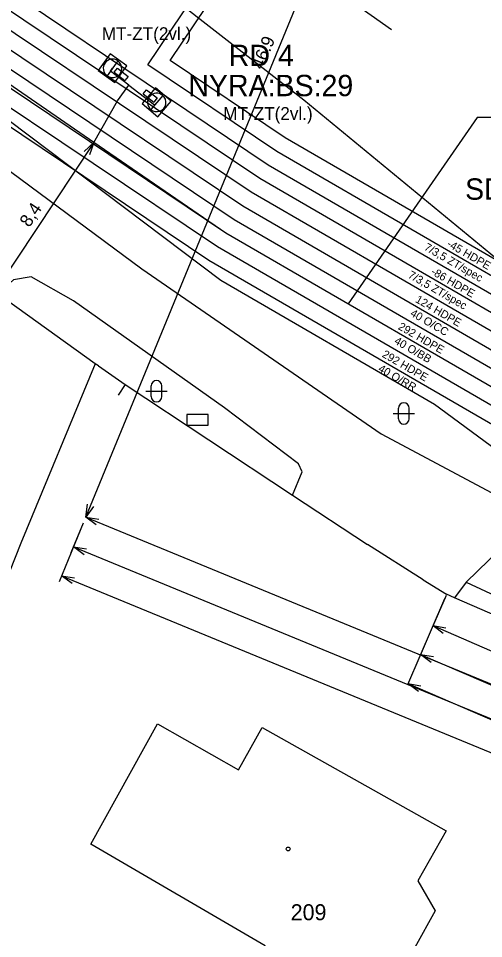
# Model space of a CAD drawing. Extents: x -836739 to -834468, y -1071001 to -1070126.
# Drawn here: x -836438.65 to -836416.85, y -1070403.2 to -1070360.1 of the extents above; entities that cross this region are included whole.
import ezdxf

# ---------------------------------------------------------------- set-up
doc = ezdxf.new("R2010")
doc.units = 0
for name, color, linetype in [('f001_pol_linie', 7, 'Continuous'), ('f001_pol_texty', 7, 'Continuous'), ('f001_pol_znacky', 7, 'Continuous'), ('f002_inz_linie_mimo_CETIN', 7, 'Continuous'), ('f003_opt_sit_texty', 7, 'Continuous'), ('f003_opt_sit_znacky', 7, 'Continuous'), ('f003_vynaseci_cary', 7, 'Continuous'), ('f006_osa_trasy', 7, 'Continuous'), ('f006_stp_koty', 7, 'Continuous'), ('f007_rezkynet_linie', 7, 'Continuous'), ('f309_trubicka', 7, 'Continuous'), ('f309_trubicka_ann', 7, 'Continuous'), ('f309_trubka', 7, 'Continuous'), ('f309_trubka_ann', 7, 'Continuous')]:
    doc.layers.add(name, color=color, linetype=linetype)

msp = doc.modelspace()

# ---------------------------------------------------------------- linework, layer by layer
at = {"layer": 'f001_pol_linie'}
for points in [[(-836356.62, -1070406.87), (-836370.19, -1070399.44), (-836385.43, -1070392.2), (-836396.38, -1070386.03), (-836404.41, -1070381.11), (-836409.87, -1070376.61), (-836425.28, -1070363.93), (-836449.03, -1070345.44), (-836455, -1070340), (-836462.64, -1070329.11), (-836464.81, -1070325.47), (-836465.74, -1070321.03), (-836464.89, -1070314.87), (-836461.62, -1070306.74), (-836456.41, -1070297.54), (-836450.95, -1070288.2), (-836447.03, -1070272.79), (-836441.38, -1070260.76)], [(-836496.52, -1070319.54), (-836488.05, -1070326.94), (-836479.74, -1070333.71), (-836473.51, -1070339.57), (-836464.27, -1070347.56), (-836456.25, -1070354.2), (-836445.54, -1070362.45), (-836432.86, -1070371.82), (-836421.65, -1070379.55), (-836415.3, -1070382.95)], [(-836490.91, -1070321.78), (-836479.74, -1070331.15), (-836472.55, -1070338.03), (-836463.6, -1070345.51), (-836457.27, -1070350.28), (-836449.01, -1070356.39), (-836440.87, -1070363.54), (-836429.17, -1070372.36), (-836419.16, -1070378.17), (-836410.31, -1070384.67), (-836403.72, -1070387.61), (-836401.28, -1070388.23), (-836398.49, -1070390.5), (-836396.2, -1070392.51)], [(-836425.81, -1070382.43), (-836425.36, -1070381.34), (-836425.52, -1070380.96), (-836428.99, -1070378.33), (-836436.06, -1070373.33), (-836438.05, -1070372.2), (-836438.88, -1070372.34), (-836439.62, -1070372.99)], [(-836435.05, -1070376.27), (-836439.62, -1070372.99)], [(-836435.05, -1070376.27), (-836439.62, -1070372.99)], [(-836435.05, -1070376.27), (-836438.54, -1070384.68), (-836445.25, -1070401.61), (-836449.39, -1070412.25)], [(-836434.9, -1070376.37), (-836435.05, -1070376.27)], [(-836434.9, -1070376.37), (-836435.05, -1070376.27)], [(-836434.9, -1070376.37), (-836433.65, -1070377.25), (-836425.81, -1070382.43)], [(-836425.81, -1070382.43), (-836422.29, -1070384.74)], [(-836415.3, -1070382.95), (-836416.08, -1070384.95), (-836417.67, -1070386.5), (-836418.22, -1070387.23)], [(-836419.68, -1070386.4), (-836422.29, -1070384.74)], [(-836419.68, -1070386.4), (-836422.29, -1070384.74)], [(-836419.68, -1070386.4), (-836418.59, -1070387.07)], [(-836419.68, -1070386.4), (-836418.59, -1070387.07)], [(-836417.67, -1070386.5), (-836404.61, -1070392.58), (-836394.98, -1070396.26), (-836377.21, -1070403.49), (-836366.86, -1070407.51), (-836361.89, -1070409.63)], [(-836393.4, -1070397.9), (-836405, -1070392.97), (-836414.08, -1070389.04), (-836418.22, -1070387.23), (-836418.59, -1070387.07)], [(-836427.22, -1070393.31), (-836418.61, -1070398.15), (-836419.94, -1070400.5), (-836419.12, -1070401.9), (-836420.07, -1070403.62), (-836421.72, -1070403.64), (-836423.01, -1070405.92), (-836423.64, -1070405.55), (-836424.86, -1070406.28), (-836427.06, -1070405.06), (-836427.09, -1070403.54), (-836435.26, -1070398.78), (-836432.13, -1070393.14), (-836428.33, -1070395.3), (-836427.22, -1070393.31)]]:
    msp.add_lwpolyline(points, dxfattribs=at)
at = {"layer": 'f001_pol_znacky'}
for p, q in [((-836432.43, -1070377.81), (-836432.43, -1070377.31)), ((-836431.93, -1070377.81), (-836431.93, -1070377.31)), ((-836432.68, -1070377.56), (-836431.68, -1070377.56)), ((-836421.09, -1070378.6), (-836420.09, -1070378.6)), ((-836420.84, -1070378.85), (-836420.84, -1070378.35)), ((-836420.34, -1070378.85), (-836420.34, -1070378.35))]:
    msp.add_line(p, q, dxfattribs=at)
msp.add_lwpolyline([(-836430.76, -1070379.15), (-836429.76, -1070379.15), (-836429.76, -1070378.65), (-836430.76, -1070378.65)], close=True, dxfattribs=at)
msp.add_lwpolyline([(-836430.76, -1070379.15), (-836429.76, -1070379.15), (-836429.76, -1070378.65), (-836430.76, -1070378.65)], close=True, dxfattribs=at)
msp.add_circle((-836426.01, -1070399), 0.0875, dxfattribs=at)
for centre, start, end in [((-836432.18, -1070377.31), 0, 180), ((-836432.18, -1070377.81), 180, 360), ((-836420.59, -1070378.35), 0, 180), ((-836420.59, -1070378.85), 180, 360)]:
    msp.add_arc(centre, 0.25, start, end, dxfattribs=at)
at = {"layer": 'f002_inz_linie_mimo_CETIN'}
for points in [[(-836434.16, -1070362.62), (-836434.01, -1070362.42), (-836433.5, -1070362.81), (-836433.66, -1070363.01)], [(-836434.16, -1070362.62), (-836434.01, -1070362.42), (-836433.5, -1070362.81), (-836433.66, -1070363.01)], [(-836434.16, -1070362.62), (-836433.66, -1070363.01)], [(-836434.16, -1070362.62), (-836433.66, -1070363.01)], [(-836432.8, -1070363.63), (-836432.64, -1070363.44), (-836432.15, -1070363.82), (-836432.3, -1070364.02)], [(-836432.8, -1070363.63), (-836432.64, -1070363.44), (-836432.15, -1070363.82), (-836432.3, -1070364.02)], [(-836432.8, -1070363.63), (-836432.3, -1070364.02)], [(-836432.8, -1070363.63), (-836432.3, -1070364.02)], [(-836434.9, -1070376.37), (-836433.65, -1070377.25)], [(-836433.65, -1070377.25), (-836433.98, -1070377.74)]]:
    msp.add_lwpolyline(points, dxfattribs=at)
at = {"layer": 'f003_opt_sit_znacky'}
for p, q in [((-836433.987, -1070362.08), (-836434.493, -1070362.78)), ((-836433.987, -1070362.081), (-836433.987, -1070362.08)), ((-836431.889, -1070363.702), (-836432.451, -1070364.358)), ((-836431.889, -1070363.703), (-836431.889, -1070363.702))]:
    msp.add_line(p, q, dxfattribs=at)
for points in [[(-836434.908, -1070362.539), (-836434.13, -1070363.102), (-836433.568, -1070362.324), (-836434.346, -1070361.761)], [(-836432.845, -1070364.084), (-836432.116, -1070364.708), (-836431.491, -1070363.98), (-836432.22, -1070363.355)]]:
    msp.add_lwpolyline(points, close=True, dxfattribs=at)
for centre, start, end in [((-836434.238, -1070362.432), 54.4817, 233.7541), ((-836434.238, -1070362.432), 233.7133, 54.5216), ((-836432.168, -1070364.032), 49.7625, 229.0349), ((-836432.168, -1070364.032), 228.9942, 49.8024)]:
    msp.add_arc(centre, 0.432, start, end, dxfattribs=at)
at = {"layer": 'f003_vynaseci_cary'}
msp.add_lwpolyline([(-836414.11, -1070364.74), (-836417.15, -1070364.74), (-836423.2, -1070373.46)], dxfattribs=at)
at = {"layer": 'f006_osa_trasy'}
for points in [[(-836435.11, -1070365.91), (-836440.26, -1070362.37), (-836446.35, -1070358.45), (-836455.55, -1070351.02), (-836461.95, -1070346), (-836466.74, -1070341.81)], [(-836433.48, -1070363.23), (-836434.34, -1070362.56), (-836434.24, -1070362.43)], [(-836435.11, -1070365.91), (-836434, -1070363.95), (-836433.48, -1070363.23)], [(-836433.48, -1070363.23), (-836432.27, -1070364.14), (-836432.17, -1070364.03)], [(-836408, -1070382.27), (-836428.93, -1070370.15), (-836435.11, -1070365.91)]]:
    msp.add_lwpolyline(points, dxfattribs=at)
at = {"layer": 'f006_stp_koty'}
for p, q in [((-836435.143, -1070365.96), (-836440.781, -1070374.433)), ((-836435.11, -1070365.91), (-836439.759, -1070372.897)), ((-836418.68, -1070387.28), (-836420.423, -1070391.31)), ((-836418.68, -1070387.28), (-836419.831, -1070389.94)), ((-836418.614, -1070387.125), (-836419.255, -1070388.592)), ((-836419.231, -1070388.537), (-836412.102, -1070391.652)), ((-836419.807, -1070389.885), (-836411.529, -1070393.464)), ((-836420.399, -1070391.255), (-836412.066, -1070394.858))]:
    msp.add_line(p, q, dxfattribs=at)
for points in [[(-836435.495, -1070383.458), (-836417.654, -1070340.121)], [(-836435.567, -1070366.326), (-836435.11, -1070365.91), (-836435.317, -1070366.493)], [(-836435.127, -1070382.96), (-836435.495, -1070383.458), (-836435.405, -1070382.846)], [(-836435.609, -1070383.735), (-836436.74, -1070386.482)], [(-836435.609, -1070383.735), (-836436.184, -1070385.132)], [(-836435.495, -1070383.458), (-836373.991, -1070408.776)], [(-836434.997, -1070383.825), (-836435.495, -1070383.458), (-836434.883, -1070383.547)], [(-836436.07, -1070384.855), (-836369.694, -1070412.179)], [(-836435.572, -1070385.222), (-836436.07, -1070384.855), (-836435.458, -1070384.944)], [(-836436.625, -1070386.205), (-836366.711, -1070414.986)], [(-836436.127, -1070386.572), (-836436.625, -1070386.205), (-836436.013, -1070386.294)], [(-836418.741, -1070388.915), (-836419.231, -1070388.537), (-836418.621, -1070388.64)], [(-836419.316, -1070390.26), (-836419.807, -1070389.885), (-836419.197, -1070389.985)], [(-836419.908, -1070391.631), (-836420.399, -1070391.255), (-836419.789, -1070391.355)]]:
    msp.add_lwpolyline(points, dxfattribs=at)
at = {"layer": 'f007_rezkynet_linie'}
msp.add_lwpolyline([(-836421.168, -1070360.637), (-836435.606, -1070350.43), (-836434.733, -1070348.728)], dxfattribs=at)
at = {"layer": 'f309_trubicka'}
for points in [[(-836402.147, -1070370.441), (-836402.99, -1070373.112), (-836405.43, -1070380.833), (-836407.034, -1070380.23), (-836427.739, -1070368.239), (-836444.982, -1070356.659), (-836465.205, -1070339.123), (-836461.7, -1070334.81), (-836465.016, -1070332.115), (-836463.81, -1070330.63)], [(-836400.273, -1070369.489), (-836402.644, -1070369.527), (-836403.705, -1070372.886), (-836405.907, -1070379.853), (-836406.712, -1070379.55), (-836427.342, -1070367.602), (-836444.526, -1070356.062), (-836464.165, -1070339.032), (-836460.645, -1070334.701), (-836463.961, -1070332.006), (-836463.228, -1070331.103)], [(-836400.273, -1070369.489), (-836403.36, -1070369.301), (-836404.42, -1070372.66), (-836406.384, -1070378.872), (-836406.39, -1070378.87), (-836426.945, -1070366.965), (-836444.07, -1070355.465), (-836463.125, -1070338.941), (-836460.063, -1070335.174), (-836456.969, -1070337.689), (-836456.236, -1070336.787)], [(-836400.273, -1070369.489), (-836404.075, -1070369.075), (-836405.135, -1070372.434), (-836406.818, -1070377.756), (-836426.548, -1070366.328), (-836432.585, -1070362.274), (-836428.785, -1070356.615), (-836431.381, -1070354.872), (-836430.736, -1070353.911)], [(-836400.273, -1070369.489), (-836404.79, -1070368.849), (-836405.85, -1070372.208), (-836407.251, -1070376.638), (-836426.151, -1070365.691), (-836431.544, -1070362.069), (-836428.162, -1070357.033), (-836425.302, -1070358.953), (-836424.657, -1070357.993)]]:
    msp.add_lwpolyline(points, dxfattribs=at)
at = {"layer": 'f309_trubka'}
for points in [[(-836257.543, -1070422.322), (-836258.258, -1070422.096), (-836259.283, -1070421.772), (-836260.99, -1070422.47), (-836266.6, -1070439.21), (-836271.52, -1070438.59), (-836350.1, -1070406.54), (-836380.46, -1070395.41), (-836397.84, -1070386.09), (-836408, -1070382.27), (-836428.93, -1070370.15), (-836446.35, -1070358.45), (-836497.8, -1070313.84), (-836500.259, -1070310.812)], [(-836499.139, -1070311.001), (-836497.259, -1070313.316), (-836445.894, -1070357.853), (-836428.533, -1070369.513), (-836407.678, -1070381.59), (-836397.529, -1070385.406), (-836380.152, -1070394.724), (-836349.829, -1070405.84), (-836271.328, -1070437.858), (-836267.116, -1070438.389), (-836261.592, -1070421.906), (-836259.316, -1070420.975), (-836258.032, -1070421.38), (-836257.317, -1070421.606)], [(-836500.901, -1070311.21), (-836500.428, -1070311.792), (-836498.049, -1070311.154), (-836496.718, -1070312.792), (-836445.438, -1070357.256), (-836428.136, -1070368.876), (-836407.356, -1070380.91), (-836404.953, -1070381.813), (-836402.275, -1070373.338)], [(-836501.069, -1070312.194), (-836498.882, -1070314.888), (-836447.262, -1070359.644), (-836429.724, -1070371.424), (-836408.644, -1070383.63), (-836398.462, -1070387.458), (-836381.076, -1070396.782), (-836350.642, -1070407.94), (-836271.904, -1070440.054), (-836265.568, -1070440.852), (-836259.786, -1070423.598), (-836259.218, -1070423.366), (-836257.995, -1070423.753)], [(-836499.902, -1070312.441), (-836498.341, -1070314.364), (-836446.806, -1070359.047), (-836429.327, -1070370.787), (-836408.322, -1070382.95), (-836398.151, -1070386.774), (-836380.768, -1070396.096), (-836350.371, -1070407.24), (-836271.712, -1070439.322), (-836266.084, -1070440.031), (-836260.388, -1070423.034), (-836259.25, -1070422.569), (-836257.769, -1070423.038)]]:
    msp.add_lwpolyline(points, dxfattribs=at)

# ---------------------------------------------------------------- texts
at = {"layer": 'f001_pol_texty'}
msp.add_text('209', height=0.75, dxfattribs=at).set_placement((-836425.89, -1070402.34))
at = {"layer": 'f003_opt_sit_texty'}
for s, height, p in [('MT-ZT(2vl.)', 0.6, (-836434.74, -1070361.11)), ('RD 4', 1, (-836428.79, -1070362.33)), ('NYRA:BS:29', 1, (-836430.69, -1070363.74)), ('MT-ZT(2vl.)', 0.6, (-836429.05, -1070364.85)), ('SDF Kamenný Újezd', 1, (-836417.72, -1070368.59))]:
    msp.add_text(s, height=height, dxfattribs=at).set_placement(p)
at = {"layer": 'f006_stp_koty'}
for s, rotation, p in [('46.9', 67.63, (-836427.204, -1070362.53)), ('8,4', 56.362, (-836438.136, -1070369.916))]:
    msp.add_text(s, height=0.6, rotation=rotation, dxfattribs=at).set_placement(p)
at = {"layer": 'f309_trubicka_ann'}
for s, rotation, p in [('7/3,5 ZT/spec', 329.9197, (-836419.673, -1070370.917)), ('-45 HDPE', 329.9197, (-836418.608, -1070370.754)), ('7/3,5 ZT/spec', 329.9224, (-836420.425, -1070372.215)), ('-86 HDPE', 329.9224, (-836419.352, -1070372.056))]:
    msp.add_text(s, height=0.375, rotation=rotation, dxfattribs=at).set_placement(p)
at = {"layer": 'f309_trubka_ann'}
for s, rotation, p in [('124 HDPE', 329.9242, (-836420.083, -1070373.366)), ('40 O/CC', 329.9242, (-836420.323, -1070374.007)), ('292 HDPE', 329.926, (-836420.89, -1070374.633)), ('40 O/BB', 329.926, (-836421.075, -1070375.305)), ('292 HDPE', 329.9278, (-836421.642, -1070375.931)), ('40 O/RR', 329.9278, (-836421.827, -1070376.603))]:
    msp.add_text(s, height=0.375, rotation=rotation, dxfattribs=at).set_placement(p)

doc.saveas('drawing.dxf')
